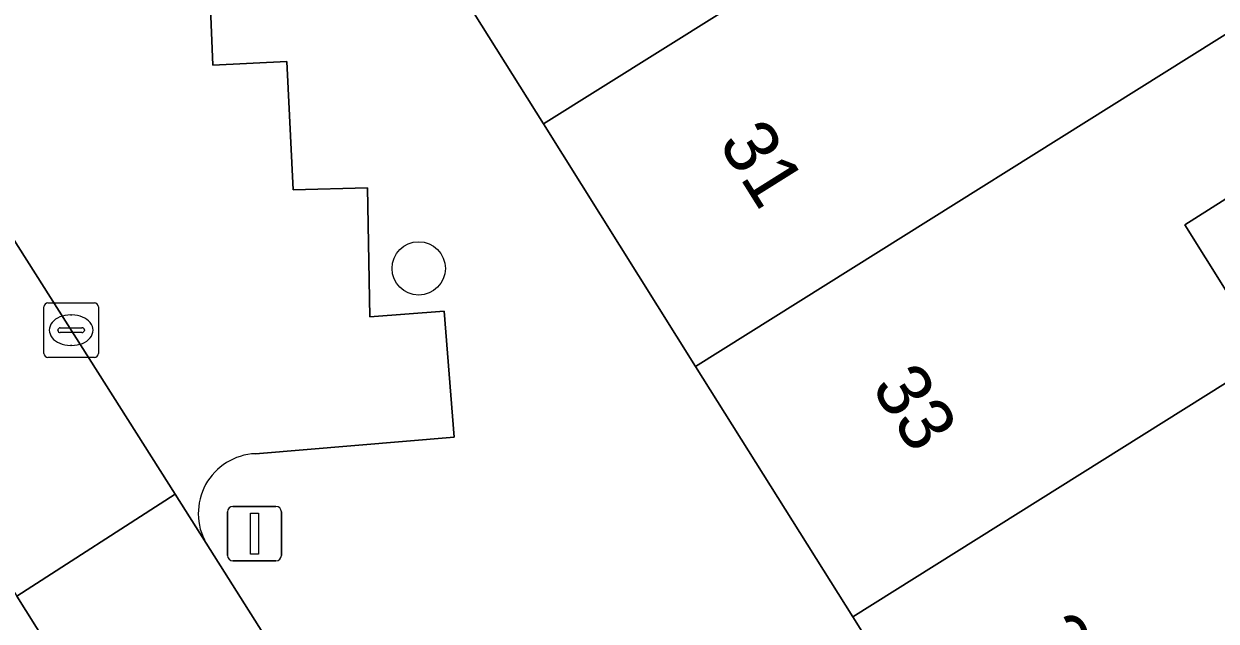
# Model space of a CAD drawing. Extents: x 161798 to 162385, y 382315 to 382833.
# Drawn here: x 162076.75 to 162098.63, y 382526.34 to 382537.31 of the extents above; entities that cross this region are included whole.
import ezdxf

# ---------------------------------------------------------------- set-up
doc = ezdxf.new("R2010")
doc.units = 0
for name, color, linetype in [('IMGEO_Boom', 7, 'Continuous'), ('IMGEO_Erf', 7, 'Continuous'), ('IMGEO_Kolk', 7, 'Continuous'), ('IMGEO_Lichtmast', 7, 'Continuous'), ('IMGEO_Pand', 7, 'Continuous'), ('IMGEO_Pand_nummerreeks', 7, 'Continuous'), ('IMGEO_Parkeervlak_open', 7, 'Continuous'), ('IMGEO_Rijbaan_lokaal_open', 7, 'Continuous'), ('IMGEO_Voetpad_open', 7, 'Continuous')]:
    doc.layers.add(name, color=color, linetype=linetype)

msp = doc.modelspace()

# ---------------------------------------------------------------- linework, layer by layer
at = {"layer": 'IMGEO_Boom'}
msp.add_circle((162083.999, 382532.819), 0.489, dxfattribs=at)
at = {"layer": 'IMGEO_Erf'}
msp.add_lwpolyline([(162101.435, 382535.761), (162098.057, 382533.617), (162099.576, 382531.194)], dxfattribs=at)
at = {"layer": 'IMGEO_Kolk'}
for p, q in [((162077.121, 382531.259), (162077.121, 382532.111)), ((162077.196, 382532.185), (162078.048, 382532.185)), ((162078.122, 382532.111), (162078.122, 382531.259)), ((162077.609, 382531.965), (162077.634, 382531.965)), ((162077.38, 382531.679), (162077.38, 382531.691)), ((162077.818, 382531.642), (162077.42, 382531.642)), ((162077.423, 382531.728), (162077.821, 382531.728)), ((162077.864, 382531.691), (162077.864, 382531.679)), ((162077.632, 382531.405), (162077.607, 382531.405)), ((162078.048, 382531.185), (162077.196, 382531.185))]:
    msp.add_line(p, q, dxfattribs=at)
for points in [[(162077.121, 382531.259), (162077.121, 382532.111)], [(162077.196, 382532.185), (162078.048, 382532.185)], [(162078.122, 382532.111), (162078.122, 382531.259)], [(162078.048, 382531.185), (162077.196, 382531.185)]]:
    msp.add_lwpolyline(points, dxfattribs=at)
for centre, radius, start, end in [((162077.198, 382532.109), 0.0765, 91.552, 178.448), ((162077.198, 382532.109), 0.0765, 91.552, 178.448), ((162078.046, 382532.109), 0.0765, 1.552, 88.448), ((162078.046, 382532.109), 0.0765, 1.552, 88.448), ((162077.42, 382531.688), 0.0403, 85.8775, 175.7526), ((162077.417, 382531.678), 0.0366, 178.938, 274.7102), ((162077.821, 382531.685), 0.043, 264.8664, 352.4533), ((162077.825, 382531.69), 0.0386, 1.7309, 96.639), ((162077.198, 382531.261), 0.0765, 181.552, 268.448), ((162077.198, 382531.261), 0.0765, 181.552, 268.448), ((162078.046, 382531.261), 0.0765, 271.552, 358.448), ((162078.046, 382531.261), 0.0765, 271.552, 358.448)]:
    msp.add_arc(centre, radius, start, end, dxfattribs=at)
for centre, major_axis, ratio, start_param, end_param in [((162077.608, 382531.685), (-0.387, 0.002), 0.722429, 4.712389, 7.853982), ((162077.633, 382531.685), (-0.39, 0.002), 0.717154, 1.570796, 4.712389)]:
    msp.add_ellipse(centre, major_axis=major_axis, ratio=ratio, start_param=start_param, end_param=end_param, dxfattribs=at)
at = {"layer": 'IMGEO_Lichtmast'}
for p, q in [((162080.49, 382527.551), (162080.49, 382528.351)), ((162080.49, 382528.351), (162080.49, 382527.551)), ((162080.59, 382528.451), (162081.38, 382528.451)), ((162081.38, 382528.451), (162080.59, 382528.451)), ((162081.48, 382528.351), (162081.48, 382527.551)), ((162081.48, 382527.551), (162081.48, 382528.351)), ((162081.38, 382527.451), (162080.59, 382527.451)), ((162080.59, 382527.451), (162081.38, 382527.451))]:
    msp.add_line(p, q, dxfattribs=at)
msp.add_lwpolyline([(162080.91, 382528.326), (162081.06, 382528.326), (162081.06, 382527.576), (162080.91, 382527.576), (162080.91, 382528.326)], dxfattribs=at)
for centre, start, end in [((162080.59, 382528.351), 90, 180), ((162080.59, 382528.351), 90, 180), ((162081.38, 382528.351), 0, 90), ((162081.38, 382528.351), 360, 90), ((162080.59, 382527.551), 180, 270), ((162080.59, 382527.551), 180, 270), ((162081.38, 382527.551), 270, 0), ((162081.38, 382527.551), 270, 0)]:
    msp.add_arc(centre, 0.1, start, end, dxfattribs=at)
at = {"layer": 'IMGEO_Pand'}
for points in [[(162083.278, 382540.272), (162086.288, 382535.473), (162093.902, 382540.247), (162092.286, 382542.824), (162095.664, 382544.914), (162094.271, 382547.166)], [(162100.07, 382537.912), (162098.864, 382539.812), (162095.509, 382537.683), (162093.902, 382540.247), (162086.288, 382535.473), (162089.081, 382531.02)], [(162100.07, 382537.912), (162089.081, 382531.02), (162091.965, 382526.421), (162099.576, 382531.194), (162098.057, 382533.617), (162101.435, 382535.761)], [(162099.576, 382531.194), (162091.965, 382526.421), (162094.758, 382521.967), (162105.766, 382528.87), (162104.559, 382530.785), (162101.171, 382528.649)]]:
    msp.add_lwpolyline(points, close=True, dxfattribs=at)
at = {"layer": 'IMGEO_Parkeervlak_open'}
for points in [[(162070.806, 382542.435), (162079.529, 382528.674), (162080.1, 382527.774)], [(162081.003, 382529.418), (162084.647, 382529.719), (162084.466, 382532.033), (162083.105, 382531.929), (162083.059, 382534.298), (162081.697, 382534.26), (162081.579, 382536.616), (162080.223, 382536.552), (162080.123, 382538.95)]]:
    msp.add_lwpolyline(points, dxfattribs=at)
msp.add_arc((162081.052, 382528.321), 1.098, 92.5756, 209.867, dxfattribs=at)
at = {"layer": 'IMGEO_Rijbaan_lokaal_open'}
msp.add_lwpolyline([(162055.907, 382559.825), (162061.253, 382551.291), (162061.473, 382550.939), (162062.044, 382550.029), (162062.739, 382548.921), (162076.622, 382526.804), (162079.529, 382528.674), (162070.806, 382542.435), (162069.1, 382545.165), (162066.2, 382549.805)], dxfattribs=at)
msp.add_lwpolyline([(162079.529, 382528.674), (162076.622, 382526.804), (162078.203, 382524.285), (162081.138, 382526.129), (162080.1, 382527.774)], close=True, dxfattribs=at)
at = {"layer": 'IMGEO_Voetpad_open'}
for points in [[(162100.624, 382512.613), (162097.64, 382517.372), (162094.758, 382521.967), (162091.965, 382526.421), (162089.081, 382531.02), (162086.288, 382535.473), (162083.278, 382540.272), (162080.568, 382544.594), (162078.994, 382547.104), (162078.097, 382546.514), (162078.51, 382545.898), (162074.54, 382543.391), (162072.092, 382547.296), (162070.298, 382550.02), (162067.877, 382553.694), (162067.7, 382553.581), (162067.224, 382554.323), (162060.346, 382565.051), (162057.798, 382563.184), (162058.339, 382562.28), (162058.445, 382562.115), (162058.477, 382562.063), (162058.51, 382562.012)], [(162054.599, 382561.171), (162051.863, 382559.469), (162058.602, 382548.668), (162058.995, 382548.046), (162062.305, 382542.767), (162065.729, 382537.304), (162069.305, 382531.6), (162072.69, 382526.201), (162073.232, 382525.358), (162076.885, 382519.522), (162079.956, 382521.492), (162078.203, 382524.285), (162076.622, 382526.804)], [(162066.263, 382552.747), (162066.474, 382552.754), (162067.642, 382550.881), (162066.13, 382549.916), (162066.2, 382549.805), (162066.597, 382550.051), (162069.427, 382545.515), (162070.549, 382546.192), (162073.822, 382541.04), (162078.659, 382541.261), (162078.76, 382538.898), (162080.123, 382538.95), (162080.223, 382536.552), (162081.579, 382536.616), (162081.697, 382534.26), (162083.059, 382534.298), (162083.105, 382531.929), (162084.466, 382532.033), (162084.647, 382529.719), (162081.003, 382529.418)], [(162080.1, 382527.774), (162081.138, 382526.129), (162081.227, 382525.987)]]:
    msp.add_lwpolyline(points, dxfattribs=at)
msp.add_arc((162081.052, 382528.321), 1.098, 92.5756, 209.867, dxfattribs=at)

# ---------------------------------------------------------------- texts
at = {"layer": 'IMGEO_Pand_nummerreeks'}
for s, p in [('31', (162089.487, 382535.115)), ('33', (162092.292, 382530.642)), ('35', (162095.157, 382526.073))]:
    msp.add_text(s, height=1, rotation=302.0927, dxfattribs=at).set_placement(p)

doc.saveas('drawing.dxf')
